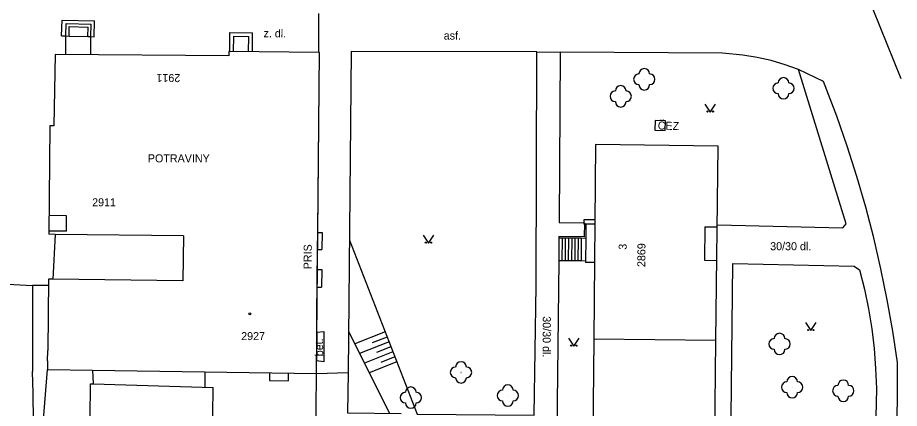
# Model space of a CAD drawing. Extents: x -584400 to -581602, y -1210894 to -1208793.
# Drawn here: x -583059.9 to -582977.3, y -1210447.2 to -1210410.6 of the extents above; entities that cross this region are included whole.
import ezdxf

# ---------------------------------------------------------------- set-up
doc = ezdxf.new("R2010")
doc.units = 0
for name, color, linetype in [('BUDOVY_MĚŘ', 7, 'Continuous'), ('POMOC_POPIS', 7, 'Continuous'), ('ROZHRANÍ_PLOCH', 7, 'Continuous'), ('VÝŠKOPIS', 7, 'Continuous'), ('ZELEŇ', 7, 'Continuous'), ('ZN_BUDOV', 7, 'Continuous'), ('ZN_DOPLŇKOVÉ', 7, 'Continuous'), ('ZN_KULTUR', 7, 'Continuous'), ('Č_POPIS_EVID', 7, 'Continuous')]:
    doc.layers.add(name, color=color, linetype=linetype)

msp = doc.modelspace()

# ---------------------------------------------------------------- linework, layer by layer
at = {"layer": 'BUDOVY_MĚŘ'}
for points in [[(-583031.87, -1210443.89), (-583031.59, -1210413.86), (-583040.08, -1210413.77), (-583040.08, -1210414.16), (-583056.35, -1210414.05), (-583056.47, -1210420.72), (-583056.85, -1210420.72), (-583056.93, -1210430.87)], [(-583031.75, -1210430.76), (-583031.75, -1210430.7), (-583031.59, -1210413.86)], [(-582994.45, -1210440.82), (-582994.25, -1210422.62), (-583005.72, -1210422.46), (-583005.88, -1210440.69)], [(-583056.34, -1210430.88), (-583056.93, -1210430.87)], [(-583044.33, -1210431), (-583044.38, -1210435.21), (-583056.55, -1210435.08)], [(-583044.33, -1210431), (-583056.34, -1210430.88)], [(-583031.82, -1210438.38), (-583031.76, -1210432.28), (-583031.76, -1210432.13)], [(-583056.55, -1210435.08), (-583056.97, -1210435.07), (-583057.04, -1210441.73)], [(-583031.84, -1210440.03), (-583031.83, -1210439.46)], [(-583005.88, -1210440.69), (-583006.07, -1210458.68)], [(-582994.45, -1210440.82), (-583005.88, -1210440.69)], [(-582994.65, -1210458.81), (-582994.45, -1210440.82)], [(-583057.05, -1210442.7), (-583057.06, -1210443.53), (-583052.86, -1210443.59)], [(-583031.87, -1210443.89), (-583031.87, -1210442.72)], [(-583052.86, -1210443.59), (-583031.87, -1210443.89)], [(-583053.37, -1210480.54), (-583053.58, -1210499.56), (-583042.06, -1210499.7), (-583041.64, -1210452.88), (-583041.53, -1210445.2)], [(-583053.37, -1210480.54), (-583053.02, -1210444.86), (-583052.77, -1210444.87)], [(-583052.77, -1210444.87), (-583041.53, -1210445.2)]]:
    msp.add_lwpolyline(points, dxfattribs=at)
at = {"layer": 'ROZHRANÍ_PLOCH'}
for points in [[(-582977.11, -1210416.31), (-582980.37, -1210408.19)], [(-583055.74, -1210412.3), (-583055.7, -1210410.83), (-583052.65, -1210410.9)], [(-583052.99, -1210412.37), (-583052.69, -1210412.38), (-583052.65, -1210410.9)], [(-583031.66, -1210413.86), (-583031.64, -1210410.22)], [(-583055.34, -1210412.31), (-583055.31, -1210411.14), (-583052.96, -1210411.2)], [(-583055.04, -1210412.32), (-583055.02, -1210411.44), (-583053.26, -1210411.49)], [(-583053.29, -1210412.36), (-583053.26, -1210411.49)], [(-583052.99, -1210412.37), (-583052.96, -1210411.2)], [(-583055.74, -1210412.3), (-583055.34, -1210412.31)], [(-583055.35, -1210414.06), (-583055.34, -1210412.31)], [(-583055.34, -1210412.31), (-583055.04, -1210412.32)], [(-583055.04, -1210412.32), (-583053.29, -1210412.36)], [(-583053.29, -1210412.36), (-583053.03, -1210412.37)], [(-583053.03, -1210412.37), (-583053.04, -1210414.07)], [(-583053.03, -1210412.37), (-583052.99, -1210412.37)], [(-583039.99, -1210413.77), (-583039.97, -1210411.99), (-583037.86, -1210412.01)], [(-583039.64, -1210413.77), (-583039.62, -1210412.34), (-583038.21, -1210412.35)], [(-583038.22, -1210413.79), (-583038.21, -1210412.35)], [(-583037.87, -1210413.79), (-583037.86, -1210412.01)], [(-583022.44, -1210447.69), (-583011.47, -1210447.79), (-583011.29, -1210435.68), (-583011.23, -1210413.8), (-583028.62, -1210413.77), (-583028.91, -1210443.81)], [(-583011.23, -1210413.8), (-583009.04, -1210413.82)], [(-582994.32, -1210429.97), (-582982.58, -1210430.27), (-582982.24, -1210429.88), (-582986.71, -1210415.45), (-582987.98, -1210415), (-582989.28, -1210414.62), (-582990.59, -1210414.32), (-582991.92, -1210414.1), (-582993.84, -1210413.92), (-583009.04, -1210413.82), (-583009.15, -1210429.76)], [(-582977.5, -1210449.41), (-582977.43, -1210446.23), (-582977.45, -1210442.88), (-582977.89, -1210439.94), (-582978.4, -1210437.01), (-582979, -1210434.09), (-582979.67, -1210431.2), (-582980.42, -1210428.32), (-582981.25, -1210425.46), (-582982.15, -1210422.63), (-582983.13, -1210419.82), (-582984.37, -1210416.58), (-582986.71, -1210415.45)], [(-583055.28, -1210430.59), (-583055.27, -1210429.13), (-583056.92, -1210429.12)], [(-583009.15, -1210429.76), (-583006.75, -1210429.79), (-583006.78, -1210431.12), (-583009.16, -1210431.09)], [(-583005.79, -1210429.52), (-583006.82, -1210429.51), (-583006.83, -1210429.91)], [(-583006.64, -1210429.91), (-583006.83, -1210429.91)], [(-583006.64, -1210429.91), (-583006.65, -1210431.25)], [(-583005.79, -1210429.92), (-583006.64, -1210429.91)], [(-583055.28, -1210430.59), (-583056.93, -1210430.57)], [(-582995.5, -1210430.16), (-582995.53, -1210433.29), (-582994.36, -1210433.31)], [(-582995.5, -1210430.16), (-582994.33, -1210430.17)], [(-583009.16, -1210431.23), (-583009.18, -1210433.35)], [(-583009.16, -1210431.09), (-583009.16, -1210431.23)], [(-583008.86, -1210431.23), (-583009.16, -1210431.23)], [(-583008.86, -1210431.23), (-583008.88, -1210433.35)], [(-583008.56, -1210431.23), (-583008.86, -1210431.23)], [(-583008.56, -1210431.23), (-583008.58, -1210433.35)], [(-583008.26, -1210431.23), (-583008.56, -1210431.23)], [(-583008.26, -1210431.23), (-583008.28, -1210433.35)], [(-583007.96, -1210431.23), (-583008.26, -1210431.23)], [(-583007.96, -1210431.23), (-583007.98, -1210433.35)], [(-583007.06, -1210431.24), (-583007.96, -1210431.23)], [(-583007.66, -1210431.25), (-583007.68, -1210433.35)], [(-583007.36, -1210431.25), (-583007.38, -1210433.36)], [(-583007.06, -1210431.24), (-583007.08, -1210433.36)], [(-583006.65, -1210431.25), (-583007.06, -1210431.24)], [(-583006.65, -1210431.25), (-583006.67, -1210433.37)], [(-583009.18, -1210433.35), (-583009.35, -1210449.27)], [(-583008.88, -1210433.35), (-583009.18, -1210433.35)], [(-583008.58, -1210433.35), (-583008.88, -1210433.35)], [(-583008.28, -1210433.35), (-583008.58, -1210433.35)], [(-583007.98, -1210433.35), (-583008.28, -1210433.35)], [(-583007.68, -1210433.35), (-583007.98, -1210433.35)], [(-583007.38, -1210433.36), (-583007.68, -1210433.35)], [(-583007.08, -1210433.36), (-583007.38, -1210433.36)], [(-583006.67, -1210433.37), (-583007.08, -1210433.36)], [(-583006.67, -1210433.37), (-583006.67, -1210433.51)], [(-583005.82, -1210433.52), (-583006.67, -1210433.51)], [(-582993.03, -1210447.97), (-582992.88, -1210433.59), (-582981.51, -1210433.85), (-582980.99, -1210434.19), (-582980.53, -1210436.01), (-582980.15, -1210437.85), (-582979.85, -1210439.7), (-582979.63, -1210441.56), (-582979.49, -1210443.43), (-582979.42, -1210445.31), (-582979.47, -1210447.97)], [(-583063.7, -1210435.39), (-583058.46, -1210435.65)], [(-583058.46, -1210435.65), (-583058.48, -1210443.7)], [(-583056.98, -1210435.66), (-583058.46, -1210435.65)], [(-583031.84, -1210440.03), (-583031.19, -1210439.97), (-583031.17, -1210442.81), (-583031.87, -1210442.72)], [(-583070.24, -1210491.43), (-583068.85, -1210488.95), (-583067.54, -1210486.43), (-583066.29, -1210483.87), (-583065.12, -1210481.28), (-583064.02, -1210478.66), (-583063, -1210476.01), (-583062.05, -1210473.33), (-583061.57, -1210471.9), (-583060.9, -1210469.34), (-583060.31, -1210466.76), (-583059.79, -1210464.17), (-583059.35, -1210461.56), (-583058.99, -1210458.94), (-583058.71, -1210456.31), (-583058.51, -1210453.68), (-583058.4, -1210451.03), (-583058.36, -1210448.39), (-583058.4, -1210445.75), (-583058.48, -1210443.7)], [(-583057.76, -1210452.11), (-583057.06, -1210443.53)], [(-583042.32, -1210443.74), (-583042.32, -1210445.18)], [(-583041.64, -1210452.86), (-583036.17, -1210452.79), (-583036.15, -1210454.02), (-583031.95, -1210454), (-583031.87, -1210443.89), (-583028.91, -1210443.81)], [(-583036.27, -1210443.83), (-583036.28, -1210444.55), (-583034.52, -1210444.57)], [(-583034.51, -1210443.86), (-583034.52, -1210444.57)], [(-583028.91, -1210443.81), (-583028.95, -1210447.59), (-583023.94, -1210447.64)]]:
    msp.add_lwpolyline(points, dxfattribs=at)
at = {"layer": 'VÝŠKOPIS'}
for points in [[(-583028.78, -1210431.43), (-583022.44, -1210447.69)], [(-583028.87, -1210439.94), (-583025.03, -1210447.63)], [(-583025.43, -1210440.01), (-583028.28, -1210441.12)], [(-583025.25, -1210440.48), (-583026.65, -1210441.02)], [(-583025.07, -1210440.94), (-583027.83, -1210442.02)], [(-583024.89, -1210441.41), (-583026.25, -1210441.94)], [(-583024.71, -1210441.88), (-583027.38, -1210442.92)], [(-583024.53, -1210442.34), (-583025.84, -1210442.85)], [(-583024.34, -1210442.81), (-583026.93, -1210443.82)]]:
    msp.add_lwpolyline(points, dxfattribs=at)
at = {"layer": 'ZELEŇ'}
for centre in [(-583001.16, -1210416.37), (-582988.12, -1210417.21), (-583003.37, -1210417.96), (-582988.49, -1210441.13), (-583018.33, -1210443.79), (-582987.31, -1210445.18), (-582982.52, -1210445.51), (-583023.03, -1210446.15), (-583013.94, -1210445.96)]:
    msp.add_circle(centre, 0.0005, dxfattribs=at)
for centre, start, end in [((-583001.66, -1210416.37), 89.99999, 269.99999), ((-583001.16, -1210415.87), 0, 179.99999), ((-583000.66, -1210416.37), 270, 89.99999), ((-582988.62, -1210417.21), 89.99999, 269.99999), ((-582988.12, -1210416.71), 0, 179.99999), ((-582987.62, -1210417.21), 270, 89.99999), ((-583003.87, -1210417.96), 89.99999, 269.99999), ((-583003.37, -1210417.46), 0, 179.99999), ((-583002.87, -1210417.96), 270, 89.99999), ((-583001.16, -1210416.87), 179.99999, 359.99999), ((-582988.12, -1210417.71), 179.99999, 359.99999), ((-583003.37, -1210418.46), 179.99999, 359.99999), ((-582988.99, -1210441.13), 89.99999, 269.99999), ((-582988.49, -1210440.63), 0, 179.99999), ((-582987.99, -1210441.13), 270, 89.99999), ((-582988.49, -1210441.63), 179.99999, 359.99999), ((-583018.33, -1210443.29), 0, 179.99999), ((-583018.83, -1210443.79), 89.99999, 269.99999), ((-583017.83, -1210443.79), 270, 89.99999), ((-583018.33, -1210444.29), 179.99999, 359.99999), ((-582987.81, -1210445.18), 89.99999, 269.99999), ((-582987.31, -1210444.68), 0, 179.99999), ((-582986.81, -1210445.18), 270, 89.99999), ((-582982.52, -1210445.01), 0, 179.99999), ((-583023.03, -1210445.65), 0, 179.99999), ((-583014.44, -1210445.96), 89.99999, 269.99999), ((-583013.94, -1210445.46), 0, 179.99999), ((-583013.44, -1210445.96), 270, 89.99999), ((-582983.02, -1210445.51), 89.99999, 269.99999), ((-582982.02, -1210445.51), 270, 89.99999), ((-583023.53, -1210446.15), 89.99999, 269.99999), ((-583022.53, -1210446.15), 270, 89.99999), ((-583013.94, -1210446.46), 179.99999, 359.99999), ((-582987.31, -1210445.68), 179.99999, 359.99999), ((-582982.52, -1210446.01), 179.99999, 359.99999), ((-583023.03, -1210446.65), 179.99999, 359.99999)]:
    msp.add_arc(centre, 0.5, start, end, dxfattribs=at)
at = {"layer": 'ZN_BUDOV'}
msp.add_circle((-583038.11, -1210438.32), 0.0875, dxfattribs=at)
at = {"layer": 'ZN_DOPLŇKOVÉ'}
for points in [[(-583000.14, -1210420.22), (-583000.17, -1210421.12), (-582999.21, -1210421.15), (-582999.18, -1210420.25), (-583000.14, -1210420.22)], [(-583031.76, -1210432.13), (-583031.75, -1210430.76)], [(-583031.75, -1210430.7), (-583031.34, -1210430.71), (-583031.35, -1210432.29)], [(-583056.34, -1210430.88), (-583056.55, -1210435.08)], [(-583031.76, -1210432.28), (-583031.35, -1210432.29)], [(-583031.78, -1210434.15), (-583031.37, -1210434.15), (-583031.39, -1210435.82)], [(-583031.79, -1210435.82), (-583031.39, -1210435.82)], [(-583031.83, -1210439.46), (-583031.82, -1210438.38)], [(-583031.84, -1210440.03), (-583031.87, -1210442.72)], [(-583057.05, -1210442.7), (-583057.04, -1210441.73)], [(-583052.86, -1210443.59), (-583052.77, -1210444.87)]]:
    msp.add_lwpolyline(points, dxfattribs=at)
at = {"layer": 'ZN_KULTUR'}
for points in [[(-582995.48, -1210418.68), (-582994.98, -1210419.43), (-582994.48, -1210418.68)], [(-583021.88, -1210430.95), (-583021.38, -1210431.7), (-583020.88, -1210430.95)], [(-582986.07, -1210439.13), (-582985.57, -1210439.88), (-582985.07, -1210439.13)], [(-583008.27, -1210440.59), (-583007.77, -1210441.34), (-583007.27, -1210440.59)]]:
    msp.add_lwpolyline(points, dxfattribs=at)
for centre in [(-582995.23, -1210419.38), (-582994.73, -1210419.38), (-583021.63, -1210431.65), (-583021.13, -1210431.65), (-582985.82, -1210439.83), (-582985.32, -1210439.83), (-583008.02, -1210441.29), (-583007.52, -1210441.29)]:
    msp.add_circle(centre, 0.05, dxfattribs=at)

# ---------------------------------------------------------------- texts
at = {"layer": 'POMOC_POPIS'}
for s, rotation, p in [('z. dl.', 359.38761, (-583036.83, -1210412.43)), ('asf.', 359.90115, (-583019.95, -1210412.65)), ('ČEZ', 358.21006, (-582999.91, -1210421.06)), ('PRIS', 89.46581, (-583032.33, -1210434.15)), ('30/30 dl.', 269.8429, (-583010.67, -1210438.54)), ('bet.', 90.40346, (-583031.24, -1210442.28))]:
    msp.add_text(s, height=0.75, rotation=rotation, dxfattribs=at).set_placement(p)
for s, p in [('POTRAVINY', (-583047.66, -1210424.14)), ('30/30 dl.', (-582989.37, -1210432.36))]:
    msp.add_text(s, height=0.75, dxfattribs=at).set_placement(p)
at = {"layer": 'Č_POPIS_EVID'}
for s, rotation, p in [('2911', 179.61264, (-583044.62, -1210415.88)), ('3', 89.49417, (-583002.81, -1210432.32)), ('2869', 89.49715, (-583001.07, -1210433.94))]:
    msp.add_text(s, height=0.75, rotation=rotation, dxfattribs=at).set_placement(p)
for s, p in [('2911', (-583052.88, -1210428.25)), ('2927', (-583038.92, -1210440.77))]:
    msp.add_text(s, height=0.75, dxfattribs=at).set_placement(p)

doc.saveas('drawing.dxf')
